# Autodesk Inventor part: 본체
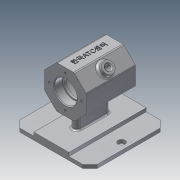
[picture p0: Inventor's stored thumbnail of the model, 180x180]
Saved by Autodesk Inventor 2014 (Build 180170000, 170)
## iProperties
Created: 2018-06
Part Number: 본체
Material: 알루미늄 6061
Document SubType Name: Modeling
Designer: sda
Mass: 553.538 g
Surface Area: 601.27 cm^2
Volume: 204.258 cm^3
Density: 2.71 g/cm^3
Appearance: 알루미늄 - 평지
Author: sda
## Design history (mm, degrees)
node "작업 평면1"
node "작업 평면2"
node "작업 평면3"
sketch "스케치2"
  geometry: L1 (12.426, 30)-(30, 12.426); L2 (30, 12.426)-(30, -12.426); L3 (30, -12.426)-(12.426, -30); L4 (12.426, -30)-(-12.426, -30); L5 (-12.426, -30)-(-30, -12.426); L6 (-30, -12.426)-(-30, 12.426); L7 (-30, 12.426)-(-12.426, 30); L8 (-12.426, 30)-(12.426, 30); 3 further points
  constraints: 16 end point, 1 horizontal, 1 midpoint, 17 other
extrude "돌출1" new body sketch "스케치2" stored distance "d4" = 70; taper "d5" = 0 deg
sketch "스케치4"
  geometry: L1 (-35, 30)-(35, 30) reference; L2 (-35, 30)-(-35, 12.426) reference; L3 (-35, 12.426)-(35, 12.426) reference; L4 (-35, 30)-(-35, 12.426) reference; L5 (-35, 30)-(35, 30) reference; L6 (35, 12.426)-(35, 30) reference; L7 (-35, -12.426)-(35, -12.426) reference; L8 (-35, 12.426)-(-35, -12.426) reference; L9 (-35, 12.426)-(35, 12.426) reference; L10 (35, -12.426)-(35, 12.426) reference; L11 (-35, -30)-(35, -30) reference; L12 (-35, -12.426)-(-35, -30) reference; L13 (-35, -12.426)-(35, -12.426) reference; L14 (35, -30)-(35, -12.426) reference; L15 (0, 25)-(20, 25); L16 (20, 25)-(20, 14); L17 (20, 14)-(23, 14); L18 (23, 14)-(23, 16); L19 (23, 16)-(35, 16); L20 (-35, 0)-(35, 0); L21 (0, 0)-(0, 30); L22 (0, 25)-(-20, 25); L23 (-20, 25)-(-20, 14); L24 (-20, 14)-(-23, 14); L25 (-23, 14)-(-23, 16); L26 (-23, 16)-(-35, 16); L27 (-35, 16)-(-35, 0); L28 (35, 16)-(35, 0)
  constraints: 28 end point, 5 symmetric about line, 3 midpoint, 2 collinear, 2 point on line, 1 perpendicular
  dimensions: "d7" = 32 diameter of L19 L20; "d8" = 50 diameter of L15 L20; "d9" = 28 diameter of L17 L20; "d10" = 12 distance of L18.end L19.end; "d11" = 3 distance of L16.end L17.end; "d13" = 11 distance of L15.end L16.end; "d14" = 32 diameter of L26 L20 (derived); "d15" = 2 distance of L24.end L25.end
revolve "회전1" sketch "스케치4" stored, may be unused: angle "d16" = 90 deg
chamfer "모따기1" distance "d17" = 1; stored, may be unused: second distance "d18" = 2, angle "d19" = 45 deg
chamfer "모따기2" distance "d20" = 1; stored, may be unused: second distance "d21" = 2, angle "d22" = 45 deg
fillet "모깎기1" dims "d23" = 0.3
fillet "모깎기2" dims "d24" = 3
node "작업 평면4"
sketch "스케치6"
  geometry: L1 (-45, 55)-(45, 55); L2 (55, 45)-(55, -45); L3 (45, -55)-(-45, -55); L4 (-55, -45)-(-55, 45); L5 (-55, 55)-(55, -55); L6 (55, 55)-(-55, -55); L7 (-45, 55)-(-55, 45); L8 (-55, -45)-(-45, -55); L9 (45, -55)-(55, -45); L10 (55, 45)-(45, 55); 3 further points
  constraints: 20 end point, 8 point on line, 4 midpoint, 2 parallel, 1 horizontal, 1 perpendicular
  dimensions: "d26" = 110 distance of L5.end L6.end; "d27" = 110 distance of L6.start L5.end; "d28" = 10 distance of L1.start L5.start; "d29" = 10 distance of L4.end L5.start (= d28); "d30" = 10 distance of L4.start L6.end (= d28); "d31" = 10 distance of L3.end L6.end (= d30); "d32" = 10 distance of L3.start L5.end (= d28); "d33" = 10 distance of L2.end L5.end (= d32); "d34" = 10 distance of L2.start L6.start (= d28); "d35" = 10 distance of L1.end L6.start (= d34)
extrude "돌출2" join sketch "스케치6" distance "d38" = 5; taper "d39" = 0 deg
sketch "스케치7"
  geometry: L1 (-45, 55)-(45, 55); L2 (55, 45)-(55, -45); L3 (45, -55)-(-45, -55); L4 (-55, -45)-(-55, 45); L5 (-55, 55)-(55, -55); L6 (55, 55)-(-55, -55); L7 (-45, 55)-(-55, 45); L8 (-55, -45)-(-45, -55); L9 (55, -45)-(45, -55); L10 (55, 45)-(45, 55); 1 further point
  constraints: 20 end point, 8 point on line, 2 midpoint, 2 parallel, 1 horizontal, 1 perpendicular
  dimensions: "d40" = 110 distance of L5.end L6.end; "d41" = 110 distance of L6.start L5.end; "d42" = 10 distance of L1.start L5.start; "d43" = 10 distance of L4.end L5.start (= d42); "d44" = 10 distance of L4.start L6.end (= d42); "d45" = 10 distance of L3.end L6.end (= d44); "d46" = 10 distance of L2.end L5.end (= d42); "d47" = 10 distance of L3.start L5.end (= d46); "d48" = 10 distance of L2.start L6.start (= d42); "d49" = 10 distance of L1.end L6.start (= d48)
extrude "돌출3" join sketch "스케치7" distance "d50" = 5; taper "d51" = 0 deg
sketch "스케치8"
  geometry: L1 (45, 55)-(-45, 55) reference; L2 (-45, -55)-(-45, 0); L3 (45, -55)-(45, 0); 1 further point
  constraints: 4 end point, 1 parallel, 1 perpendicular
sketch "스케치9"
  geometry: L1 (-25, 55)-(25, 55); L2 (25, 55)-(25, -55); L3 (25, -55)-(-25, -55); L4 (-25, -55)-(-25, 55); L5 (-25, 55)-(25, -55); L6 (25, 55)-(-25, -55); L7 (-45, -55)-(-45, 0); L8 (45, -55)-(45, 0); 3 further points
  constraints: 16 end point, 4 parallel, 2 coincident, 2 midpoint, 1 horizontal, 1 perpendicular
  dimensions: "d52" = 50 distance of L2.end L3.end; "d53" = 110 distance of L1.end L2.end
extrude "돌출4" join sketch "스케치9" distance "d54" = 5; taper "d55" = 0 deg
hole "구멍1" sketch "스케치8" diameter "d56" = 10; stored, may be unused: countersink angle "d60" = 90 deg, drill point angle "d62" = 118 deg; dims "d57" = 6, "d58" = 4, "d59" = 2, "d61" = 8
sketch "스케치10"
  geometry: L1 (5, 19)-(5, -19); L2 (-5, -19)-(-5, 19); L3 (-5, 19)-(5, -19); L4 (5, 19)-(-5, -19); A1 r 5 centre (0, 19) between (5, 19) and (-5, 19); A2 r 5 centre (0, -19) between (-5, -19) and (5, -19); 1 further point
  constraints: 8 end point, 4 point on circle, 2 centre point, 2 midpoint, 1 parallel
  dimensions: "d63" = 10 distance of L1.end L2.start; "d64" = 38 distance of L1.start L1.end
extrude "돌출5" join sketch "스케치10" stored distance "d65" = 5; taper "d66" = 0 deg
fillet "모깎기3" dims "d67" = 2
sketch "스케치11" dims "d68" = 46
  geometry: C1 r 17 at (0, 0) reference; 2 further points
  constraints: 2 vertical alignment, 1 coincident, 2 other
hole "구멍2" sketch "스케치11" at (0, 23) diameter "d69" = 3.242; stored, may be unused: countersink angle "d73" = 82 deg, drill point angle "d75" = 118 deg; dims "d70" = 8, "d71" = 3.023, "d72" = 2, "d74" = 10
node "작업 평면5"
sketch "스케치12"
  geometry: C1 r 8 at (-11.426, 35); 1 further point
  constraints: 1 centre point, 1 coincident
  dimensions: "d80" = 16 diameter of C1
extrude "돌출6" join sketch "스케치12" stored distance "d81" = 5; taper "d82" = 0 deg
sketch "스케치13"
  geometry: C1 r 8 at (0, 0) reference; C2 r 4 at (0, 0)
  constraints: 1 centre point, 1 coincident
  dimensions: "d83" = 8 diameter of C2
extrude "돌출7" cut sketch "스케치13" stored distance "d84" = 5; taper "d85" = 0 deg
fillet "모깎기4" dims "d86" = 3
chamfer "모따기3" distance "d87" = 1; stored, may be unused: second distance "d88" = 2, angle "d89" = 45 deg
node "작업 평면6"
sketch "스케치14"
  geometry: 2 further points
  constraints: 1 other
feature "엠보싱1" sketch "스케치14" dims "d91" = 0.5, "d92" = 0
node "솔리드1"
mirror "대칭1"
pattern_circular "원형 패턴1" dims angle "d77" = 360 deg
mirror "대칭2"
node "투영된 루프1"
node "투영된 루프2"
node "투영된 루프3"
other parameters: "d0" = 0, "d1" = 0, "d2" = 0, "d25" = -62, "d79" = 7, "d90" = 69
